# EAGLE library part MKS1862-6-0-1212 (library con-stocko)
Serie MKS 1850 Lötstifte In-line, Raster 2.5 mm, Stiftwannen, stehend, mit Rastlasche Source: http://www.stocko.de/de/index.php?seite=ka_rfk2_mks1850.html&rubrik=Katalog+-+RFK+2 rfk_1850.pdf
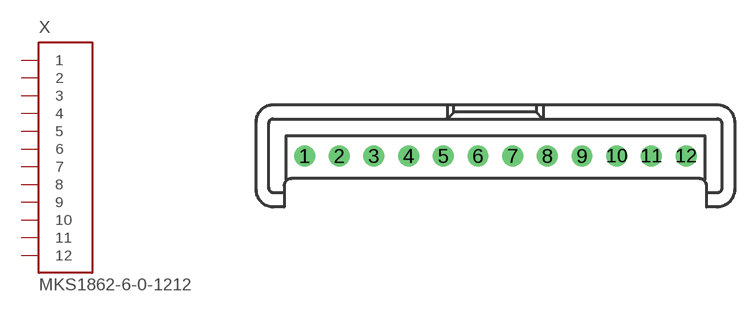
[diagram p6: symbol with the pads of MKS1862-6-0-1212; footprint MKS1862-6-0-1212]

Designator prefix X

## MKS1862-6-0-1212 (OC_FARNELL: unknown; OC_NEWARK: unknown)  [MKS1862-6-0-1212]
1  1  in
2  2  in
3  3  in
4  4  in
5  5  in
6  6  in
7  7  in
8  8  in
9  9  in
10  10  in
11  11  in
12  12  in

## Footprint MKS1862-6-0-1212 (pad centres in mm)
Serie MKS 1850 Lötstifte In-line, Raster 2.5 mm, Stiftwannen, stehend, mit Rastlasche Source: http://www.stocko.de/de/index.php?seite=ka_rfk2_mks1850.html&rubrik=Katalog+-+RFK+2 rfk_1850.pdf
drill 1 pad 1.422 round: 1 -13.75,0; 2 -11.25,0; 3 -8.75,0; 4 -6.25,0; 5 -3.75,0; 6 -1.25,0; 7 1.25,0; 8 3.75,0; 9 6.25,0; 10 8.75,0; 11 11.25,0; 12 13.75,0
